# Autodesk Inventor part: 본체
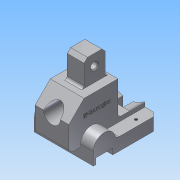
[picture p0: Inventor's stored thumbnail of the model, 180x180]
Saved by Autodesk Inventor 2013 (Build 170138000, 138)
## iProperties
Created: 2016-11
Part Number: 본체
Material: 알루미늄 6061
Document SubType Name: Modeling
Designer: Administrator
Density: 2.71 g/cm^3
Mass: 462.771 g
Surface Area: 317.516 cm^2
Volume: 170.764 cm^3
Author: Administrator
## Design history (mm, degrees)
sketch "스케치1"
  geometry: L1 (35, 38)-(-35, 38); L2 (-35, 38)-(-35, -38); L3 (-35, -38)-(35, -38); L4 (35, -38)-(35, 38); L5 (35, 38)-(-35, -38); L6 (-35, 38)-(35, -38); 1 further point
  constraints: 12 end point, 2 midpoint, 2 parallel, 1 horizontal, 1 perpendicular
  dimensions: "d0" = 70 distance of L3.end L2.end; "d1" = 76 distance of L2.end L1.end
extrude "돌출1" new body sketch "스케치1" distance "d2" = 15; taper "d3" = 0 deg
sketch "스케치2"
  geometry: L1 (0, 76)-(0, 0) reference; L2 (0, 0)-(15, 0) reference; L3 (0, 76)-(15, 76) reference; L4 (0, 73)-(7, 73); L5 (7, 73)-(7, 53); L6 (7, 53)-(0, 53); L7 (0, 53)-(0, 73); 1 further point
  constraints: 8 end point, 2 parallel, 1 collinear, 1 horizontal, 1 perpendicular
  dimensions: "d4" = 76 distance between parallel lines of L2 L3 (derived); "d5" = 3 distance between parallel lines of L4 L3; "d6" = 20 distance between parallel lines of L6 L4; "d7" = 7 distance between parallel lines of L5 L1
extrude "돌출2" cut sketch "스케치2" stored distance "d8" = 15; taper "d9" = 0 deg
sketch "스케치3"
  geometry: L1 (-15, 76)-(-15, 73) reference; L2 (0, 76)-(0, 50); A1 r 13 centre (0, 63) between (0, 50) and (0, 76); 1 further point
  constraints: 2 end point, 2 point on circle, 1 centre point, 1 parallel, 1 point on line
  dimensions: "d12" = 26 diameter of A1
extrude "돌출3" join sketch "스케치3" distance "d13" = 70; taper "d14" = 0 deg
sketch "스케치5"
  geometry: L1 (-38, 12)-(52, 12); L2 (52, 12)-(52, 42); L3 (52, 42)-(34, 60); L4 (34, 60)-(-6, 60); L5 (-6, 60)-(-6, 20); L6 (-6, 20)-(-38, 20); L7 (-38, 20)-(-38, 12); L8 (-38, 0)-(-38, 15) reference; L9 (15, 0)-(-38, 0) reference; 1 further point
  constraints: 14 end point, 4 parallel, 1 collinear, 1 horizontal, 1 perpendicular
  dimensions: "d15" = 20 distance between parallel lines of L6 L9; "d16" = 60 distance between parallel lines of L4 L9; "d17" = 48 distance between parallel lines of L4 L1; "d18" = 90 distance between parallel lines of L2 L7; "d19" = 58 distance between parallel lines of L2 L5; "d20" = 45 deg angle of L3 L4; "d21" = 30 distance of L2.end L1.end; "d22" = 18 horizontal distance of L2.end L3.end (derived)
extrude "돌출4" join sketch "스케치5" stored distance "d23" = 40; taper "d24" = 0 deg
sketch "스케치6"
  geometry: L1 (-1, 60)-(24, 60); L2 (24, 60)-(24, 90); L3 (24, 90)-(-1, 90); L4 (-1, 90)-(-1, 60); L5 (-6, 60)-(34, 60) reference; L6 (-6, 20)-(-6, 60) reference; L7 (15, 0)-(-38, 0) reference; 1 further point
  constraints: 8 end point, 2 parallel, 1 collinear, 1 horizontal, 1 perpendicular
  dimensions: "d25" = 5 distance between parallel lines of L4 L6; "d26" = 25 distance between parallel lines of L2 L4; "d27" = 90 distance between parallel lines of L3 L7
extrude "돌출5" join sketch "스케치6" stored distance "d28" = 20; taper "d29" = 0 deg
sketch "스케치7"
  geometry: L1 (55.668, 42)-(-49.043, 42); L2 (15, 0)-(-38, 0) reference; L3 (-6, 20)-(-6, 60) reference; L4 (-6, 42)-(1, 42); L5 (1, 42)-(1, 56.5); L6 (1, 56.5)-(-6, 56.5); L7 (-6, 56.5)-(-6, 42); L8 (1, 42)-(52, 42); L9 (52, 42)-(52, 52); L10 (52, 52)-(1, 52); L11 (1, 52)-(1, 42); L12 (52, 42)-(52, 12) reference; L13 (52, 12)-(38, 12) reference; 1 further point
  constraints: 18 end point, 4 parallel, 3 horizontal, 2 perpendicular, 2 point on line, 1 collinear
  dimensions: "d32" = 29 diameter of L6 L1; "d34" = 20 diameter of L10 L1; "d35" = 7 distance between parallel lines of L5 L3; "d76" = 30 distance between parallel lines of L1 L13
revolve "회전1" sketch "스케치7" stored, may be unused: angle "d36" = 90 deg
sketch "스케치8"
  geometry: L1 (-27.5, -38)-(27.5, -38); L2 (27.5, -38)-(27.5, -20); L3 (27.5, -20)-(-27.5, -20); L4 (-27.5, -20)-(-27.5, -38); L5 (-20, -38)-(20, -38) reference; 6 further points
  constraints: 8 end point, 4 coincident, 3 midpoint, 2 parallel, 1 horizontal, 1 perpendicular
  dimensions: "d37" = 18 distance between parallel lines of L3 L1; "d39" = 55 distance between parallel lines of L2 L4
hole "구멍1" sketch "스케치8" at (-27.5, -20), (27.5, -20) diameter "d40" = 3.242; stored, may be unused: countersink angle "d44" = 90 deg, drill point angle "d46" = 118 deg; dims "d41" = 16, "d42" = 4, "d43" = 2, "d45" = 8
sketch "스케치9"
  geometry: L1 (90, 24)-(60, 24) reference; L2 (0, 15)-(0, -38) reference; 2 further points
  dimensions: "d47" = 12.5 distance from line of point (77, 11.5) L1; "d48" = 77 distance from line of point (77, 11.5) L2
hole "구멍2" sketch "스케치9" at (77, 11.5) diameter "d49" = 8; stored, may be unused: countersink angle "d53" = 90 deg, drill point angle "d55" = 118 deg; dims "d50" = 16, "d51" = 4, "d52" = 2, "d54" = 8
sketch "스케치11"
  geometry: L1 (0, 0)-(70, 0) reference; L2 (29, 0)-(41, 0); L3 (41, 0)-(41, 20); L4 (41, 20)-(29, 20); L5 (29, 20)-(29, 0); L6 (15, 20)-(55, 20) reference; 4 further points
  constraints: 8 end point, 3 midpoint, 2 coincident, 2 parallel, 1 collinear, 1 horizontal, 1 perpendicular
  dimensions: "d61" = 12 distance between parallel lines of L3 L5
extrude "돌출7" cut sketch "스케치11" distance "d64" = 18; taper "d65" = 0 deg
chamfer "모따기1" distance "d66" = 5; stored, may be unused: second distance "d67" = 2, angle "d68" = 45 deg
chamfer "모따기2" distance "d69" = 4; stored, may be unused: second distance "d70" = 2, angle "d71" = 45 deg
fillet "모깎기1" dims "d72" = 3
chamfer "모따기3" distance "d73" = 1; stored, may be unused: second distance "d74" = 2, angle "d75" = 45 deg
fillet "모깎기2" dims "d77" = 3
sketch "스케치12"
  geometry: C1 r 29 at (-20, 27); C2 r 11 at (-20, 27) reference; 1 further point
  constraints: 1 centre point, 1 concentric
  dimensions: "d79" = 58 diameter of C1
extrude "돌출8" cut sketch "스케치12" distance "d80" = 18; taper "d81" = 0 deg
sketch "스케치13"
  geometry: L1 (23, -6)-(60, -6) reference; L2 (60, -6)-(60, 34) reference; 2 further points
  constraints: 1 other
  dimensions: "d82" = 25 distance from line of L1 point (42, 19); "d83" = 18 distance from line of point (42, 19) L2
feature "엠보싱1" sketch "스케치13" dims "d0" = 70, "d1" = 76, "d84" = 0.5, "d85" = 0
chamfer "모따기4" distance "d86" = 4; stored, may be unused: second distance "d87" = 2, angle "d88" = 45 deg
fillet "모깎기3" dims "d89" = 5
node "솔리드1"
